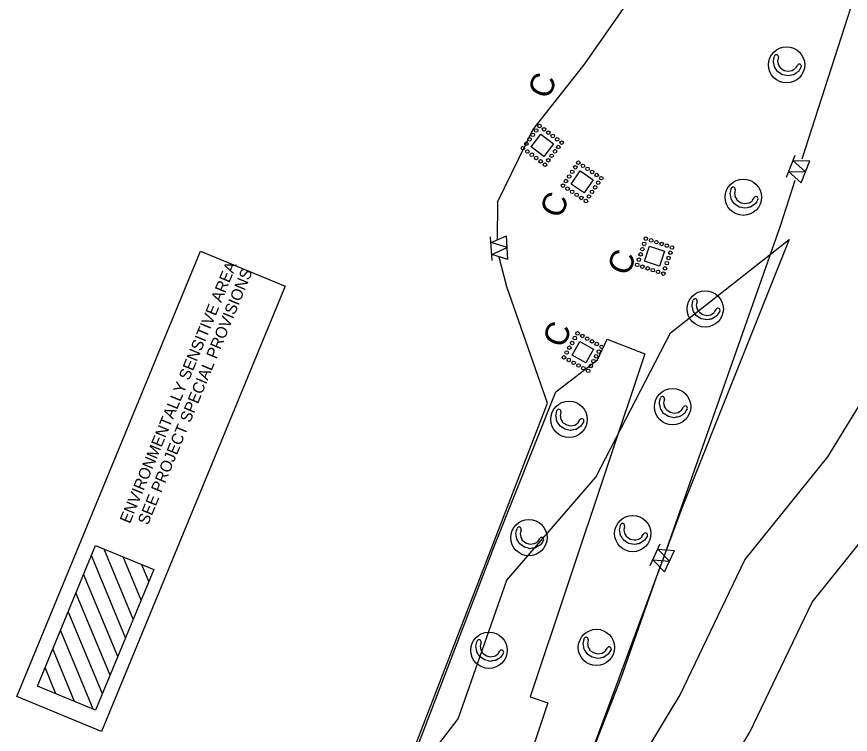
# Model space of a CAD drawing. Extents: x 2470000 to 2520000, y 340000 to 380000.
# Drawn here: x 2482707 to 2483235, y 368111 to 368565 of the extents above; entities that cross this region are included whole.
import ezdxf

# ---------------------------------------------------------------- set-up
doc = ezdxf.new("R2010")
doc.units = 0
for name, color, linetype in [('Bare Soil (Coastal) Drainage Area Border CandG Drainage', 7, 'Continuous'), ('Bare Soil (Coastal) Drainage Area Border FG Drainage', 7, 'Continuous'), ('Coir Fiber Wattle with PAM Final CELL', 7, 'Continuous'), ('Environmentally Sensitive Area Note CG CELL', 7, 'Continuous'), ('Prop Guardrail', 7, 'Continuous'), ('Scratch_Level_4', 7, 'Continuous'), ('Scratch_Level_5', 7, 'Continuous'), ('Sheet Data Field CELL', 7, 'Continuous'), ('Special Sediment Control Fence Section Both CELL', 7, 'Continuous'), ('Special Sediment Control Fence Section CG CELL', 7, 'Continuous'), ('Temporary Silt Fence CG', 7, 'Continuous')]:
    doc.layers.add(name, color=color, linetype=linetype)

# ---------------------------------------------------------------- blocks, each defined once
blk = doc.blocks.new('C3')
at = {"layer": 'Prop Guardrail'}
blk.add_text('C', height=0.3, dxfattribs=at).set_placement((-0.161, -0.136))

msp = doc.modelspace()

# ---------------------------------------------------------------- linework, layer by layer
at = {"layer": 'Bare Soil (Coastal) Drainage Area Border CandG Drainage'}
msp.add_lwpolyline([(2482886.45, 367953.41), (2482916.58, 367992.74), (2482949.4, 368071.88), (2482986.82, 368120.54), (2483017.82, 368208.47), (2483074.25, 368273.76), (2483121.41, 368365.22), (2483196.79, 368424.3), (2483128.64, 368254.09), (2483058.9, 368065.88), (2483043.08, 368010.64), (2483001.43, 367967.07), (2482934.61, 367833.16), (2482926.11, 367773.23), (2482882.08, 367800.67), (2482824.85, 367829.95), (2482832.71, 367867.61)], close=True, dxfattribs=at)
at = {"layer": 'Bare Soil (Coastal) Drainage Area Border FG Drainage'}
msp.add_lwpolyline([(2483105.28, 368351.85), (2483032.56, 368134.42), (2483043.77, 368130.67), (2483013.12, 368039.02), (2483000.04, 368007.11), (2482957.66, 367917.74), (2482910.53, 367834.56), (2482883.4, 367799.36), (2482821.93, 367830.89), (2482829.2, 367851.28), (2482882.14, 367925.38), (2482906.02, 367971.16), (2482956.56, 368090.81), (2483010.12, 368230.8), (2483048.76, 368327.75), (2483075.3, 368347.99), (2483081.39, 368361.25)], close=True, dxfattribs=at)
at = {"layer": 'Coir Fiber Wattle with PAM Final CELL'}
for p, q in [((2483189.92, 368539.74), (2483189.59, 368538.22)), ((2483189.59, 368538.22), (2483189.43, 368537.45)), ((2483189.43, 368537.45), (2483189.64, 368536.37)), ((2483189.64, 368536.37), (2483189.91, 368534.94)), ((2483190.05, 368534.75), (2483189.91, 368534.94)), ((2483190.05, 368534.75), (2483190.7, 368533.85)), ((2483200.96, 368533.04), (2483201.98, 368534.6)), ((2483191.39, 368532.88), (2483190.7, 368533.85)), ((2483191.39, 368532.88), (2483193.61, 368531.47)), ((2483193.62, 368531.46), (2483193.61, 368531.47)), ((2483193.62, 368531.46), (2483196.1, 368530.9)), ((2483196.1, 368530.9), (2483197.29, 368531.1)), ((2483197.29, 368531.1), (2483198.71, 368531.33)), ((2483198.71, 368531.33), (2483199.56, 368531.92)), ((2483199.56, 368531.92), (2483200.77, 368532.76)), ((2483200.96, 368533.04), (2483200.77, 368532.76)), ((2483162.51, 368455.88), (2483162.18, 368454.36)), ((2483162.18, 368454.36), (2483162.01, 368453.58)), ((2483162.01, 368453.58), (2483162.22, 368452.5)), ((2483162.22, 368452.5), (2483162.5, 368451.08)), ((2483162.64, 368450.89), (2483162.5, 368451.08)), ((2483162.64, 368450.89), (2483163.28, 368449.98)), ((2483163.98, 368449.02), (2483163.28, 368449.98)), ((2483173.54, 368449.18), (2483174.56, 368450.73)), ((2483163.98, 368449.02), (2483166.2, 368447.6)), ((2483166.21, 368447.6), (2483166.2, 368447.6)), ((2483166.21, 368447.6), (2483168.69, 368447.03)), ((2483168.69, 368447.03), (2483169.87, 368447.23)), ((2483169.87, 368447.23), (2483171.3, 368447.47)), ((2483171.3, 368447.47), (2483172.14, 368448.05)), ((2483172.14, 368448.05), (2483173.36, 368448.9)), ((2483173.54, 368449.18), (2483173.36, 368448.9)), ((2483138.02, 368383.55), (2483137.85, 368382.78)), ((2483137.85, 368382.78), (2483138.06, 368381.7)), ((2483138.35, 368385.07), (2483138.02, 368383.55)), ((2483138.06, 368381.7), (2483138.34, 368380.27)), ((2483138.48, 368380.08), (2483138.34, 368380.27)), ((2483138.48, 368380.08), (2483139.13, 368379.18)), ((2483139.82, 368378.21), (2483139.13, 368379.18)), ((2483139.82, 368378.21), (2483142.04, 368376.8)), ((2483142.05, 368376.79), (2483142.04, 368376.8)), ((2483142.05, 368376.79), (2483144.53, 368376.23)), ((2483144.53, 368376.23), (2483145.72, 368376.43)), ((2483145.72, 368376.43), (2483147.14, 368376.66)), ((2483147.14, 368376.66), (2483147.99, 368377.25)), ((2483147.99, 368377.25), (2483149.2, 368378.09)), ((2483149.38, 368378.37), (2483149.2, 368378.09)), ((2483149.38, 368378.37), (2483150.4, 368379.93)), ((2483117.65, 368323.13), (2483117.32, 368321.62)), ((2483117.32, 368321.62), (2483117.15, 368320.84)), ((2483117.15, 368320.84), (2483117.37, 368319.76)), ((2483117.37, 368319.76), (2483117.64, 368318.34)), ((2483117.78, 368318.14), (2483117.64, 368318.34)), ((2483117.78, 368318.14), (2483118.43, 368317.24)), ((2483119.12, 368316.27), (2483118.43, 368317.24)), ((2483128.69, 368316.43), (2483129.71, 368317.99)), ((2483051.67, 368313.57), (2483051.51, 368312.8)), ((2483051.51, 368312.8), (2483051.72, 368311.71)), ((2483052, 368315.09), (2483051.67, 368313.57)), ((2483119.12, 368316.27), (2483121.34, 368314.86)), ((2483121.35, 368314.86), (2483121.34, 368314.86)), ((2483121.35, 368314.86), (2483123.83, 368314.29)), ((2483123.83, 368314.29), (2483125.02, 368314.49)), ((2483125.02, 368314.49), (2483126.44, 368314.73)), ((2483126.44, 368314.73), (2483127.29, 368315.31)), ((2483127.29, 368315.31), (2483128.5, 368316.16)), ((2483128.69, 368316.43), (2483128.5, 368316.16)), ((2483051.72, 368311.71), (2483052, 368310.29)), ((2483052.13, 368310.1), (2483052, 368310.29)), ((2483052.13, 368310.1), (2483052.78, 368309.19)), ((2483053.48, 368308.23), (2483052.78, 368309.19)), ((2483053.48, 368308.23), (2483055.69, 368306.81)), ((2483055.7, 368306.81), (2483055.69, 368306.81)), ((2483055.7, 368306.81), (2483058.18, 368306.25)), ((2483059.37, 368306.44), (2483060.8, 368306.68)), ((2483060.8, 368306.68), (2483061.64, 368307.27)), ((2483061.64, 368307.27), (2483062.86, 368308.11)), ((2483063.04, 368308.39), (2483062.86, 368308.11)), ((2483063.04, 368308.39), (2483064.06, 368309.94)), ((2483058.18, 368306.25), (2483059.37, 368306.44)), ((2483026.38, 368238.86), (2483026.18, 368238.09)), ((2483026.18, 368238.09), (2483026.35, 368237)), ((2483026.77, 368240.36), (2483026.38, 368238.86)), ((2483092.05, 368241.22), (2483091.89, 368240.44)), ((2483091.89, 368240.44), (2483092.1, 368239.36)), ((2483092.38, 368242.73), (2483092.05, 368241.22)), ((2483092.1, 368239.36), (2483092.37, 368237.93)), ((2483092.51, 368237.74), (2483092.37, 368237.93)), ((2483026.35, 368237), (2483026.58, 368235.56)), ((2483026.71, 368235.37), (2483026.58, 368235.56)), ((2483026.71, 368235.37), (2483027.32, 368234.44)), ((2483027.98, 368233.45), (2483027.32, 368234.44)), ((2483027.98, 368233.45), (2483030.15, 368231.95)), ((2483036.1, 368232.18), (2483037.35, 368232.98)), ((2483037.54, 368233.25), (2483037.35, 368232.98)), ((2483037.54, 368233.25), (2483038.62, 368234.77)), ((2483092.51, 368237.74), (2483093.16, 368236.84)), ((2483093.85, 368235.87), (2483093.16, 368236.84)), ((2483093.85, 368235.87), (2483096.07, 368234.46)), ((2483096.08, 368234.45), (2483096.07, 368234.46)), ((2483096.08, 368234.45), (2483098.56, 368233.89)), ((2483098.56, 368233.89), (2483099.75, 368234.09)), ((2483099.75, 368234.09), (2483101.17, 368234.32)), ((2483101.17, 368234.32), (2483102.02, 368234.91)), ((2483102.02, 368234.91), (2483103.23, 368235.76)), ((2483103.42, 368236.03), (2483103.23, 368235.76)), ((2483103.42, 368236.03), (2483104.44, 368237.59)), ((2483030.16, 368231.95), (2483030.15, 368231.95)), ((2483030.16, 368231.95), (2483032.61, 368231.29)), ((2483032.61, 368231.29), (2483033.8, 368231.44)), ((2483033.8, 368231.44), (2483035.24, 368231.63)), ((2483035.24, 368231.63), (2483036.1, 368232.18)), ((2483069.35, 368170.59), (2483069.02, 368169.07)), ((2483001.04, 368167.47), (2483000.84, 368166.7)), ((2483000.84, 368166.7), (2483001.01, 368165.61)), ((2483001.01, 368165.61), (2483001.24, 368164.17)), ((2483001.43, 368168.97), (2483001.04, 368167.47)), ((2483001.37, 368163.98), (2483001.24, 368164.17)), ((2483001.37, 368163.98), (2483001.98, 368163.05)), ((2483069.02, 368169.07), (2483068.85, 368168.3)), ((2483068.85, 368168.3), (2483069.06, 368167.21)), ((2483069.06, 368167.21), (2483069.34, 368165.79)), ((2483069.48, 368165.6), (2483069.34, 368165.79)), ((2483069.48, 368165.6), (2483070.13, 368164.69)), ((2483070.82, 368163.73), (2483070.13, 368164.69)), ((2483080.39, 368163.89), (2483081.4, 368165.45)), ((2483002.64, 368162.06), (2483001.98, 368163.05)), ((2483002.64, 368162.06), (2483004.8, 368160.56)), ((2483004.81, 368160.56), (2483004.8, 368160.56)), ((2483004.81, 368160.56), (2483007.27, 368159.9)), ((2483007.27, 368159.9), (2483008.46, 368160.05)), ((2483008.46, 368160.05), (2483009.9, 368160.24)), ((2483009.9, 368160.24), (2483010.76, 368160.79)), ((2483010.76, 368160.79), (2483012.01, 368161.59)), ((2483012.2, 368161.86), (2483012.01, 368161.59)), ((2483012.2, 368161.86), (2483013.28, 368163.38)), ((2483070.82, 368163.73), (2483073.04, 368162.31)), ((2483073.05, 368162.31), (2483073.04, 368162.31)), ((2483073.05, 368162.31), (2483075.53, 368161.75)), ((2483075.53, 368161.75), (2483076.72, 368161.94)), ((2483076.72, 368161.94), (2483078.14, 368162.18)), ((2483078.14, 368162.18), (2483078.99, 368162.77)), ((2483078.99, 368162.77), (2483080.2, 368163.61)), ((2483080.39, 368163.89), (2483080.2, 368163.61))]:
    msp.add_line(p, q, dxfattribs=at)
for points in [[(2483204.38, 368533.61), (2483203.54, 368532.29), (2483202.57, 368530.76), (2483201.89, 368530.28), (2483201.06, 368529.7), (2483199.59, 368528.67), (2483199.55, 368528.66), (2483199.11, 368528.58), (2483199.04, 368528.56), (2483198.1, 368528.39), (2483197.45, 368528.26), (2483196.01, 368527.99), (2483194.99, 368528.2), (2483192.49, 368528.72), (2483192.48, 368528.72), (2483190.27, 368530.17), (2483189.41, 368530.73), (2483188.78, 368531.67), (2483188.64, 368531.87), (2483188.11, 368532.66), (2483187.7, 368533.27), (2483187.6, 368533.41), (2483187.4, 368533.72), (2483187.39, 368533.72), (2483187.12, 368535.21), (2483186.88, 368536.53), (2483186.74, 368537.33), (2483187.08, 368539.05), (2483187.39, 368540.57)], [(2483176.96, 368449.74), (2483176.13, 368448.43), (2483175.16, 368446.89), (2483174.47, 368446.41), (2483173.64, 368445.83), (2483172.17, 368444.8), (2483172.13, 368444.79), (2483171.7, 368444.71), (2483171.62, 368444.7), (2483170.68, 368444.52), (2483170.03, 368444.4), (2483168.59, 368444.12), (2483167.57, 368444.33), (2483165.07, 368444.85), (2483165.06, 368444.85), (2483162.86, 368446.3), (2483162, 368446.87), (2483161.36, 368447.8), (2483161.23, 368448), (2483160.69, 368448.8), (2483160.28, 368449.4), (2483160.19, 368449.54), (2483159.98, 368449.85), (2483159.98, 368449.86), (2483159.71, 368451.34), (2483159.47, 368452.66), (2483159.32, 368453.46), (2483159.67, 368455.18), (2483159.98, 368456.7)], [(2483152.8, 368378.94), (2483151.97, 368377.62), (2483151, 368376.09), (2483150.31, 368375.61), (2483149.48, 368375.03), (2483148.01, 368374), (2483147.97, 368373.99), (2483147.54, 368373.91), (2483147.47, 368373.89), (2483146.53, 368373.72), (2483145.87, 368373.59), (2483144.43, 368373.32), (2483143.41, 368373.53), (2483140.92, 368374.05), (2483140.91, 368374.05), (2483138.7, 368375.5), (2483137.84, 368376.06), (2483137.21, 368377), (2483137.07, 368377.2), (2483136.53, 368377.99), (2483136.13, 368378.6), (2483136.03, 368378.74), (2483135.82, 368379.04), (2483135.82, 368379.05), (2483135.55, 368380.54), (2483135.31, 368381.86), (2483135.16, 368382.66), (2483135.51, 368384.38), (2483135.82, 368385.89)], [(2483132.1, 368317), (2483131.27, 368315.68), (2483130.3, 368314.15), (2483129.62, 368313.67), (2483128.79, 368313.09), (2483127.32, 368312.06), (2483127.28, 368312.05), (2483126.84, 368311.97), (2483126.77, 368311.96), (2483125.83, 368311.78), (2483125.18, 368311.65), (2483123.74, 368311.38), (2483122.71, 368311.59), (2483120.22, 368312.11), (2483120.21, 368312.11), (2483118, 368313.56), (2483117.14, 368314.12), (2483116.51, 368315.06), (2483116.37, 368315.26), (2483115.84, 368316.06), (2483115.43, 368316.66), (2483115.33, 368316.8), (2483115.13, 368317.11), (2483115.12, 368317.11), (2483114.85, 368318.6), (2483114.61, 368319.92), (2483114.47, 368320.72), (2483114.81, 368322.44), (2483115.12, 368323.96)], [(2483066.46, 368308.95), (2483065.62, 368307.64), (2483064.65, 368306.1), (2483063.97, 368305.62), (2483063.14, 368305.04), (2483061.67, 368304.01), (2483061.63, 368304.01), (2483061.2, 368303.92), (2483061.12, 368303.91), (2483060.18, 368303.73), (2483059.53, 368303.61), (2483058.09, 368303.34), (2483057.07, 368303.54), (2483054.57, 368304.06), (2483054.56, 368304.07), (2483052.35, 368305.51), (2483051.49, 368306.08), (2483050.86, 368307.01), (2483050.73, 368307.21), (2483050.19, 368308.01), (2483049.78, 368308.61), (2483049.69, 368308.76), (2483049.48, 368309.06), (2483049.48, 368309.07), (2483049.2, 368310.55), (2483048.96, 368311.87), (2483048.82, 368312.67), (2483049.17, 368314.39), (2483049.47, 368315.91)], [(2483106.84, 368236.6), (2483106, 368235.28), (2483105.03, 368233.75), (2483104.35, 368233.27), (2483103.52, 368232.69), (2483102.05, 368231.66), (2483102.01, 368231.65), (2483101.57, 368231.57), (2483101.5, 368231.55), (2483100.56, 368231.38), (2483099.91, 368231.25), (2483098.47, 368230.98), (2483097.45, 368231.19), (2483094.95, 368231.71), (2483094.94, 368231.71), (2483092.73, 368233.16), (2483091.87, 368233.72), (2483091.24, 368234.66), (2483091.1, 368234.86), (2483090.57, 368235.65), (2483090.16, 368236.26), (2483090.06, 368236.4), (2483089.86, 368236.71), (2483089.85, 368236.71), (2483089.58, 368238.2), (2483089.34, 368239.52), (2483089.2, 368240.32), (2483089.54, 368242.04), (2483089.85, 368243.56)], [(2483040.98, 368233.69), (2483040.1, 368232.4), (2483039.07, 368230.91), (2483038.37, 368230.45), (2483037.52, 368229.9), (2483036.01, 368228.93), (2483035.97, 368228.93), (2483035.53, 368228.86), (2483035.46, 368228.85), (2483034.51, 368228.7), (2483033.86, 368228.61), (2483032.41, 368228.39), (2483031.4, 368228.64), (2483028.92, 368229.25), (2483028.91, 368229.25), (2483026.76, 368230.78), (2483025.92, 368231.37), (2483025.32, 368232.34), (2483025.19, 368232.54), (2483024.69, 368233.35), (2483024.3, 368233.97), (2483024.21, 368234.12), (2483024.02, 368234.43), (2483024.02, 368234.44), (2483023.8, 368235.93), (2483023.61, 368237.26), (2483023.49, 368238.06), (2483023.91, 368239.77), (2483024.27, 368241.28)], [(2483015.64, 368162.3), (2483014.76, 368161.01), (2483013.73, 368159.52), (2483013.03, 368159.06), (2483012.18, 368158.52), (2483010.67, 368157.54), (2483010.63, 368157.54), (2483010.19, 368157.47), (2483010.12, 368157.46), (2483009.17, 368157.32), (2483008.52, 368157.22), (2483007.07, 368157), (2483006.05, 368157.25), (2483003.58, 368157.86), (2483003.57, 368157.86), (2483001.42, 368159.39), (2483000.58, 368159.98), (2482999.98, 368160.95), (2482999.85, 368161.15), (2482999.35, 368161.96), (2482998.96, 368162.58), (2482998.87, 368162.73), (2482998.68, 368163.04), (2482998.67, 368163.05), (2482998.46, 368164.54), (2482998.27, 368165.87), (2482998.15, 368166.67), (2482998.57, 368168.38), (2482998.93, 368169.89)], [(2483083.8, 368164.45), (2483082.97, 368163.14), (2483082, 368161.6), (2483081.31, 368161.12), (2483080.49, 368160.54), (2483079.02, 368159.51), (2483078.98, 368159.51), (2483078.54, 368159.42), (2483078.47, 368159.41), (2483077.53, 368159.23), (2483076.87, 368159.11), (2483075.43, 368158.84), (2483074.41, 368159.05), (2483071.92, 368159.56), (2483071.91, 368159.57), (2483069.7, 368161.01), (2483068.84, 368161.58), (2483068.21, 368162.52), (2483068.07, 368162.71), (2483067.53, 368163.51), (2483067.13, 368164.11), (2483067.03, 368164.26), (2483066.83, 368164.56), (2483066.82, 368164.57), (2483066.55, 368166.05), (2483066.31, 368167.37), (2483066.17, 368168.17), (2483066.51, 368169.89), (2483066.82, 368171.41)]]:
    msp.add_lwpolyline(points, dxfattribs=at)
for centre in [(2483195.09, 368534.97), (2483167.67, 368451.11), (2483143.51, 368380.3), (2483122.82, 368318.36), (2483057.17, 368310.32), (2483097.55, 368237.96), (2483031.75, 368235.4), (2483006.41, 368164.01), (2483074.52, 368165.82)]:
    msp.add_circle(centre, 11.5, dxfattribs=at)
for centre, radius, start, end in [((2483188.63, 368540.06), 1.33, 346.4504, 157.5631), ((2483203.18, 368534.1), 1.3, 337.5631, 157.5631), ((2483161.21, 368456.19), 1.33, 346.4504, 157.5631), ((2483175.76, 368450.24), 1.3, 337.5631, 157.5631), ((2483137.05, 368385.39), 1.33, 346.4504, 157.5631), ((2483151.6, 368379.43), 1.3, 337.5631, 157.5631), ((2483116.35, 368323.45), 1.33, 346.4504, 157.5631), ((2483130.9, 368317.5), 1.3, 337.5631, 157.5631), ((2483050.71, 368315.4), 1.33, 346.4504, 157.5631), ((2483065.26, 368309.45), 1.3, 337.5631, 157.5631), ((2483091.09, 368243.05), 1.33, 346.4504, 157.5631), ((2483025.48, 368240.72), 1.33, 344.3047, 155.4174), ((2483105.64, 368237.09), 1.3, 337.5631, 157.5631), ((2483039.8, 368234.23), 1.3, 335.4174, 155.4174), ((2483000.14, 368169.33), 1.33, 344.3047, 155.4174), ((2483068.05, 368170.9), 1.33, 346.4504, 157.5631), ((2483014.46, 368162.84), 1.3, 335.4174, 155.4174), ((2483082.6, 368164.95), 1.3, 337.5631, 157.5631)]:
    msp.add_arc(centre, radius, start, end, dxfattribs=at)
at = {"layer": 'Environmentally Sensitive Area Note CG CELL'}
for p, q in [((2482720.12, 368141.26), (2482756.93, 368230.41)), ((2482756.93, 368230.41), (2482793.89, 368215.13)), ((2482780.96, 368183.82), (2482762.57, 368228.06)), ((2482776.06, 368171.96), (2482754.34, 368224.13)), ((2482785.85, 368195.66), (2482774.48, 368223.14)), ((2482790.75, 368207.53), (2482786.34, 368218.25)), ((2482771.17, 368160.11), (2482749.44, 368212.28)), ((2482793.89, 368215.13), (2482757.08, 368125.99)), ((2482766.27, 368148.25), (2482744.55, 368200.44)), ((2482761.37, 368136.4), (2482739.65, 368188.57)), ((2482755.57, 368126.62), (2482734.76, 368176.71)), ((2482743.66, 368131.54), (2482729.86, 368164.86)), ((2482731.8, 368136.43), (2482724.97, 368153)), ((2482757.08, 368125.99), (2482720.12, 368141.26))]:
    msp.add_line(p, q, dxfattribs=at)
msp.add_lwpolyline([(2482707, 368134.63), (2482823.59, 368416.97), (2482877.32, 368394.78), (2482760.73, 368112.44)], close=True, dxfattribs=at)
at = {"layer": 'Scratch_Level_4'}
for points in [[(2483085.04, 368065.06), (2483127.66, 368135.84), (2483168.66, 368221.22), (2483221.15, 368286.55), (2483276.76, 368377.26), (2483355.23, 368406.68), (2483371.87, 368418.81), (2483452.82, 368525.26), (2483555.67, 368592.37), (2483775.05, 368610.58), (2483826.84, 368610.97)], [(2483098.83, 368010.77), (2483127.36, 368038.42), (2483171.71, 368112.07), (2483211.24, 368194.39), (2483262.11, 368257.71), (2483310.4, 368336.47), (2483379.17, 368362.25), (2483407.24, 368382.72), (2483487.39, 368488.11), (2483572.4, 368543.59), (2483777.32, 368560.59), (2483827.22, 368560.98)]]:
    msp.add_lwpolyline(points, dxfattribs=at)
at = {"layer": 'Scratch_Level_5'}
for points in [[(2483033.23, 368482.94), (2483039.22, 368490.95), (2483047.23, 368484.96), (2483041.22, 368476.96)], [(2483058.57, 368459.45), (2483064.14, 368467.75), (2483072.44, 368462.17), (2483066.86, 368453.88)], [(2483105.1, 368410.6), (2483108.28, 368420.08), (2483117.76, 368416.9), (2483114.57, 368407.42)], [(2483059.11, 368351.05), (2483064, 368359.77), (2483072.72, 368354.89), (2483067.83, 368346.17)]]:
    msp.add_lwpolyline(points, close=True, dxfattribs=at)
for centre in [(2483038.45, 368496.2), (2483034.25, 368490.6), (2483036.35, 368493.4), (2483041.25, 368494.11), (2483044.05, 368492.01), (2483032.15, 368487.8), (2483046.85, 368489.91), (2483049.65, 368487.81), (2483052.46, 368485.71), (2483027.96, 368482.2), (2483030.06, 368485), (2483030.76, 368480.1), (2483048.26, 368480.11), (2483050.36, 368482.91), (2483033.56, 368478), (2483036.36, 368475.9), (2483046.16, 368477.31), (2483039.17, 368473.8), (2483041.97, 368471.71), (2483044.06, 368474.51), (2483061.15, 368470.05), (2483063.1, 368472.96), (2483066.01, 368471.01), (2483057.25, 368464.24), (2483059.2, 368467.15), (2483068.91, 368469.05), (2483071.82, 368467.1), (2483074.72, 368465.15), (2483055.29, 368461.34), (2483075.68, 368460.29), (2483077.63, 368463.2), (2483053.34, 368458.43), (2483056.25, 368456.48), (2483059.15, 368454.53), (2483071.77, 368454.48), (2483073.72, 368457.39), (2483062.06, 368452.58), (2483064.96, 368450.62), (2483067.87, 368448.67), (2483069.82, 368451.58), (2483105.9, 368424.83), (2483109.22, 368423.71), (2483112.53, 368422.6), (2483103.67, 368418.19), (2483104.78, 368421.51), (2483115.85, 368421.49), (2483119.17, 368420.38), (2483122.49, 368419.26), (2483101.45, 368411.55), (2483102.56, 368414.87), (2483120.26, 368412.63), (2483121.38, 368415.95), (2483100.33, 368408.23), (2483103.65, 368407.12), (2483106.97, 368406.01), (2483118.04, 368405.99), (2483119.15, 368409.31), (2483110.29, 368404.9), (2483113.61, 368403.78), (2483116.93, 368402.67), (2483062.54, 368364.88), (2483059.12, 368358.77), (2483060.83, 368361.83), (2483065.59, 368363.17), (2483068.65, 368361.46), (2483071.7, 368359.75), (2483057.41, 368355.72), (2483074.75, 368358.04), (2483076.1, 368353.27), (2483077.81, 368356.33), (2483053.99, 368349.61), (2483055.7, 368352.67), (2483057.04, 368347.9), (2483074.39, 368350.22), (2483060.09, 368346.19), (2483063.15, 368344.48), (2483066.2, 368342.77), (2483070.97, 368344.11), (2483072.68, 368347.17), (2483069.25, 368341.06)]:
    msp.add_circle(centre, 1.12, dxfattribs=at)
at = {"layer": 'Sheet Data Field CELL'}
for p, q in [((2483067.16, 368535.66), (2483094.75, 368574.88)), ((2483034.23, 368493.72), (2483067.32, 368535.87)), ((2483011.88, 368447.93), (2483034.23, 368493.72)), ((2483011.88, 368447.93), (2483011.69, 368424.02))]:
    msp.add_line(p, q, dxfattribs=at)
at = {"layer": 'Special Sediment Control Fence Section Both CELL'}
for p, q in [((2483008.42, 368411.08), (2483007.48, 368426.05)), ((2483018.4, 368411.71), (2483017.47, 368426.68))]:
    msp.add_line(p, q, dxfattribs=at)
for points in [[(2483017.93, 368419.19), (2483007.72, 368422.31), (2483017.47, 368426.68)], [(2483018.4, 368411.71), (2483008.18, 368414.83), (2483017.93, 368419.19)]]:
    msp.add_lwpolyline(points, dxfattribs=at)
at = {"layer": 'Special Sediment Control Fence Section CG CELL'}
for p, q in [((2483195.04, 368463.87), (2483200.5, 368477.84)), ((2483204.35, 368460.23), (2483209.81, 368474.2)), ((2483108.7, 368217.83), (2483114.92, 368231.48)), ((2483117.79, 368213.68), (2483124.02, 368227.33))]:
    msp.add_line(p, q, dxfattribs=at)
for points in [[(2483207.08, 368467.22), (2483199.13, 368474.35), (2483209.81, 368474.2)], [(2483204.35, 368460.23), (2483196.4, 368467.36), (2483207.08, 368467.22)], [(2483120.91, 368220.5), (2483113.37, 368228.07), (2483124.02, 368227.33)], [(2483117.79, 368213.68), (2483110.25, 368221.24), (2483120.91, 368220.5)]]:
    msp.add_lwpolyline(points, dxfattribs=at)
at = {"layer": 'Temporary Silt Fence CG'}
for points in [[(2483204.9, 368475.35), (2483236.12, 368571.69), (2483273.41, 368581.33), (2483305.92, 368598.47), (2483320.28, 368610.11)], [(2483191.2, 368433.06), (2483200.56, 368461.96)], [(2483119.29, 368228.99), (2483191.2, 368433.06)], [(2482948.39, 368074.3), (2483043.5, 368320.59), (2483017.67, 368394.38), (2483012.85, 368413.2)], [(2483044.94, 368012.83), (2483057.9, 368063.69), (2483090.26, 368146.6), (2483115.26, 368217.56)]]:
    msp.add_lwpolyline(points, dxfattribs=at)

# ---------------------------------------------------------------- block references
at = {"layer": 'Scratch_Level_5', "xscale": 50, "yscale": 49.99999999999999, "rotation": 67.56305879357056}
for p in [(2483041.1, 368522.57), (2483048.76, 368446.97), (2483091.42, 368410.54), (2483050.52, 368364.88)]:
    msp.add_blockref('C3', p, dxfattribs=at)

# ---------------------------------------------------------------- texts
at = {"layer": 'Environmentally Sensitive Area Note CG CELL'}
for s, p in [('ENVIRONMENTALLY SENSITIVE AREA', (2482778.77, 368243.83)), ('SEE PROJECT SPECIAL PROVISIONS', (2482790.17, 368242.91))]:
    msp.add_text(s, height=7.26, rotation=67.5687, dxfattribs=at).set_placement(p)

doc.saveas('drawing.dxf')
